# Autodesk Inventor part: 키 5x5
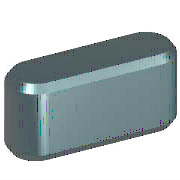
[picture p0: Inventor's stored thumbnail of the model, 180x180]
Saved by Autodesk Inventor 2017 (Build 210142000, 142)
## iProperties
IsCustomPart: 1
Created: 2012-02
Part Number: 키 5x5
Material: 강철, 연강
Description: 키 및 해당 키홈
Document SubType Name: Modeling
Standard: KS B 1311
Designer: mduedu
Standards Organization: KS
Language: ko-KR
Size Designation: 5 x 5 x 16
Categories: <MemberInstance><Categories><Category DisplayName="샤프트 부품" InternalName="7f7aeb1f-a693-4053-b835-cee3144e0d98" Mnemonic="SHFT"><Category DisplayName="키" Interna
Density: 1 g/cm^3
Appearance: 노란색
Author: mduedu
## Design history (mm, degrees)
workplane "Work Plane1"
workplane "Work Plane2"
sketch "스케치1"
  geometry: L1 (2.5, 2.5)-(13.5, 2.5); L2 (13.5, -2.5)-(2.5, -2.5); L3 (0, 9.4)-(0, -7.4) reference; L4 (-5, 0)-(30, 0) reference; L5 (16, 0)-(16, 7); A1 r 2.5 centre (2.5, 0) between (2.5, 2.5) and (2.5, -2.5); A2 r 2.5 centre (13.5, 0) between (13.5, -2.5) and (13.5, 2.5)
  constraints: 6 end point, 5 point on circle, 4 tangent, 3 point on line, 2 centre point, 1 horizontal, 1 parallel, 1 perpendicular
  dimensions: "d0" = 2.5 radius of A1 (= 0.5 x PB); "d13" = 2.5 radius of A2 (= 0.5 x PB); "d14" = 16 distance between parallel lines of L5 L3 (= NLG)
extrude "본체1" new body sketch "스케치1" taper "d3" = 0 deg; stored distance "d4" = 10
workplane "Work Plane3"
body "Solid1"
chamfer "모따기1" distance "d8" = 0.4 (= PHH); stored, may be unused: second distance "d9" = 0.4 (= PHH), angle "d15" = 45 deg
other parameters: "d1" = -3 (= -PNT), "d2" = 2 (= PH - PNT), "NLG" = 16 [user parameter; used in 3 equation terms], "PB" = 5 [user parameter; used in 2 equation terms], "PNT" = 3 [user parameter; used in 2 equation terms], "PH" = 5 [user parameter; used in 1 equation term], "PHH" = 0.4 [user parameter; used in 2 equation terms], "d10" = 0, "d16" = 0, "d17" = 0, "d18" = 0, "WDMIN" = 12 [user parameter], "PLB2" = 16 (= NLG) [user parameter], "WDMAX" = 17 [user parameter], "PLB1" = 16 (= NLG) [user parameter], "RR" = 0.16 [user parameter], "PUEB" = 2.3 [user parameter]
